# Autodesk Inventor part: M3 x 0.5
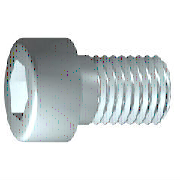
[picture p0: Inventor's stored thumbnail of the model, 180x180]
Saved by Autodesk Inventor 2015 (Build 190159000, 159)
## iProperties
IsCustomPart: 0
Created: 2015-10
Part Number: M3 x 0.5
Material: 강철, 연강
Description: 6각머리 태핑 나사
Document SubType Name: Modeling
Standard: KS B 1003
Designer: mdu
Standards Organization: KS
Language: ko-KR
Size Designation: M 3 x 12
Categories: <MemberInstance><Categories><Category DisplayName="조임쇠" InternalName="e4da775c-781d-43d5-af7c-5136215cf5a6" Mnemonic="FSTN"><Category DisplayName="볼트" InternalN
Density: 7.86 g/cm^3
Mass: 1.15208 g
Surface Area: 2.207 cm^2
Volume: 0.146575 cm^3
Appearance: 강철
Author: mdu
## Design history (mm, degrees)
sketch "스케치1"
  geometry: L1 (-0.867, 0)-(12, 0); L2 (12, 0)-(12, 1.5); L3 (12, 1.5)-(1.25, 1.5); L4 (1.25, 1.5)-(0.943, 1.5); L5 (0.943, 1.5)-(0, 1.5); L6 (0, 1.5)-(0, 2.75); L7 (0, 2.75)-(-3, 2.75); L8 (-3, 2.75)-(-3, 1.443); L9 (-3, 1.443)-(-1.7, 1.443); L10 (-1.7, 1.443)-(-0.867, 0); L11 (-6, 0)-(15, 0) reference; L12 (0, -0.55)-(0, 3.3) reference; L13 (1.25, 1.5)-(0, 1.5)
  constraints: 22 end point, 6 parallel, 2 collinear, 2 perpendicular, 1 horizontal, 1 point on line
  dimensions: "d1" = 10.75 distance from line of L3.end L2 (= GEL); "d2" = 0.30683 distance of L4.end L3.end (computed from GAL); "d3" = 3 distance between parallel lines of L8 L6 (= KOH); "d4" = 1.3 distance of L8.end L9.end (= INTI); "d5" = 60 deg angle of L10 L1; "d6" = 3 diameter of L3 L1 (= GD); "d7" = 3 diameter of L5 L1 (= BDM); "d8" = 2.88675 diameter of L9 L1 (= 1.1547 x SW); "d9" = 5.5 diameter of L7 L1 (= KOD); "d26" = 12 distance between parallel lines of L12 L2 (= NLG)
revolve "본체" sketch "스케치1" stored, may be unused: angle "d10" = 90 deg
sketch "스케치2"
  geometry: L1 (0, -3.85)-(0, 3.85) reference; L2 (-3.85, 0)-(3.85, 0) reference; L3 (1.443, 0)-(0.722, -1.25); L4 (0.722, -1.25)-(-0.722, -1.25); L5 (-0.722, -1.25)-(-1.443, 0); L6 (-1.443, 0)-(-0.722, 1.25); L7 (-0.722, 1.25)-(0.722, 1.25); L8 (0.722, 1.25)-(1.443, 0); 2 further points
  constraints: 12 end point, 1 coincident, 1 horizontal alignment, 1 point on line, 12 other
extrude "슬롯" join sketch "스케치2" stored distance "d11" = 10; taper "d12" = 0 deg
workplane "Work Plane1"
fillet "Fillet2" dims "d30" = 0.1 (= R)
body "Solid1"
fillet "모깎기1" dims "d17" = 0.3 (= RR)
feature "스레드" dims "d13" = 10.75 (= GEL), "d14" = 0
chamfer "모따기1" distance "d15" = 0.30673 (= -0.5 x SPD + 0.5 x GD); stored, may be unused: second distance "d16" = 0.30673 (= GUL), angle "d27" = 45 deg
other parameters: "GD" = 3 (= NND) [user parameter; used in 2 equation terms], "NLG" = 12 [user parameter; used in 1 equation term], "GEL" = 10.75 [user parameter; used in 2 equation terms], "KOD" = 5.5 [user parameter; used in 1 equation term], "KOH" = 3 [user parameter; used in 1 equation term], "INTI" = 1.3 [user parameter; used in 1 equation term], "GAL" = 0.30673 (= 0.61345 x PTC) [user parameter; used in 1 equation term], "GUL" = 0.30673 (= 0.61345 x PTC) [user parameter; used in 1 equation term], "BDM" = 3 (= NND) [user parameter; used in 1 equation term], "SW" = 2.5 [user parameter; used in 2 equation terms], "RR" = 0.3 [user parameter; used in 1 equation term], "SPD" = 2.38655 (= NND - 1.2269 x PTC) [user parameter; used in 1 equation term], "d19" = 0, "d28" = 0, "d29" = 0, "R" = 0.1 [user parameter; used in 1 equation term], "PHH" = 0.1 [user parameter], "GD1" = 2.38655 (= THREADDIA - 1.2269 x PTC) [user parameter], "THREADDIA" = 3 [user parameter; used in 1 equation term], "FAWI" = 45 deg [user parameter], "PTC" = 0.5 [user parameter; used in 5 equation terms], "NND" = 3 [user parameter; used in 3 equation terms], "TOA" = 30 deg [user parameter], "E0" = 2.8875 (= 1.155 x SW) [user parameter]
